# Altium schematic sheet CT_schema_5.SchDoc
size 396 x 205 mm
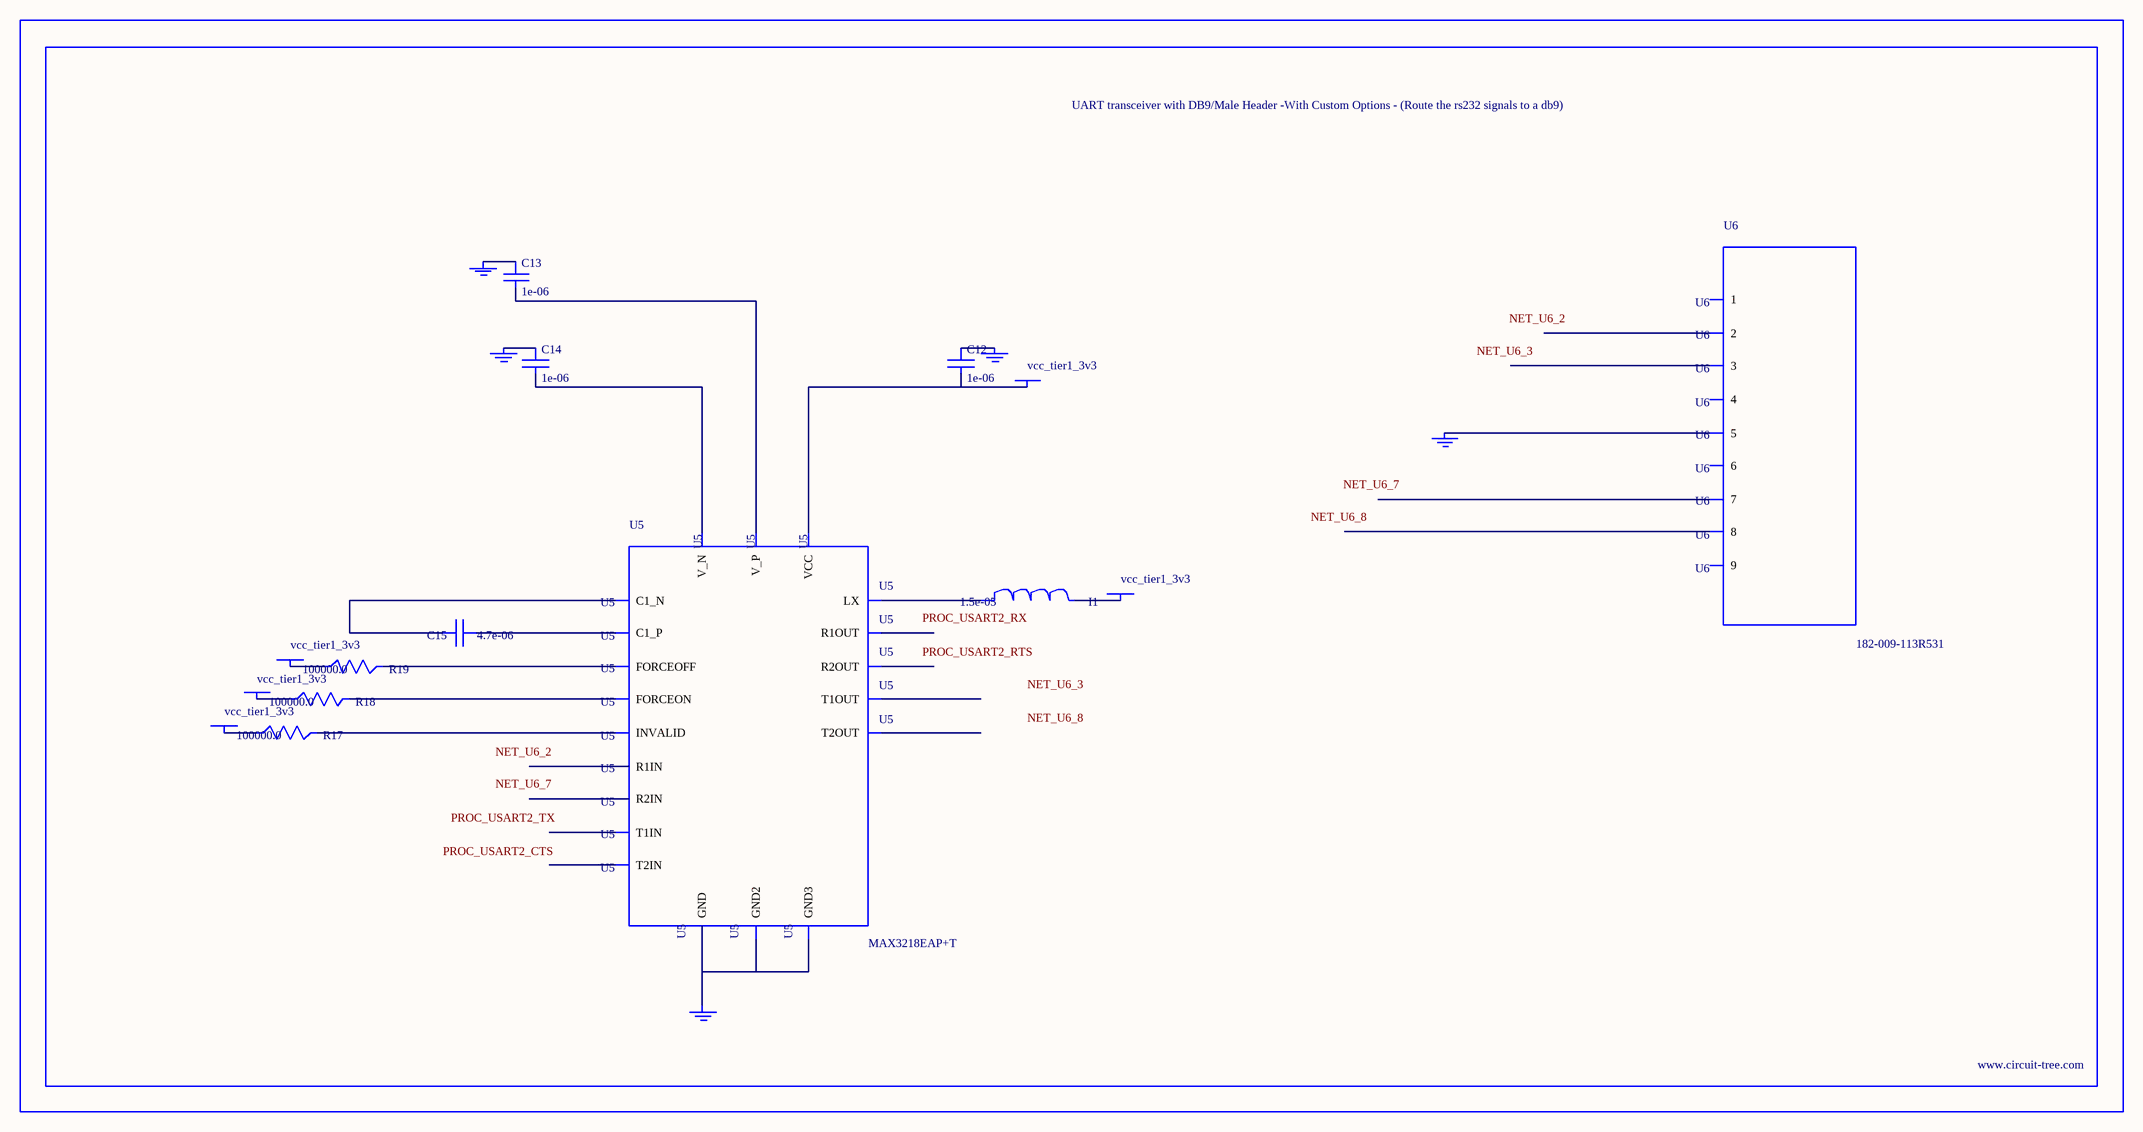
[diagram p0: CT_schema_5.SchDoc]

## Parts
BORDER4  (no value)
C12  1e-06  [C0603]
C13  1e-06  [C0603]
C14  1e-06  [C0603]
C15  4.7e-06  [C0805]
GND_INSTANCE_4_0  (no value)
GND_INSTANCE_4_1  (no value)
GND_INSTANCE_4_2  (no value)
GND_INSTANCE_4_3  (no value)
GND_INSTANCE_4_4  (no value)
I1  1.5e-05  [L1210]
POWER_INSTANCE_4_0  vcc_tier1_3v3
POWER_INSTANCE_4_1  vcc_tier1_3v3
POWER_INSTANCE_4_2  vcc_tier1_3v3
POWER_INSTANCE_4_3  vcc_tier1_3v3
POWER_INSTANCE_4_4  vcc_tier1_3v3
R17  100000.0  [R0603]
R18  100000.0  [R0603]
R19  100000.0  [R0603]
U5  MAX3218EAP+T  [SSOP-20]
U6  182-009-113R531  [182-009-MALE]

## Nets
NetC12_1: C12.1 GND_INSTANCE_4_0.0(GND)
NetC12_2: C12.2 POWER_INSTANCE_4_4.0(PWR) U5.6(VCC)
NetC13_1: C13.1 GND_INSTANCE_4_2.0(GND)
NetC13_2: C13.2 U5.19(V_P)
NetC14_1: C14.1 GND_INSTANCE_4_1.0(GND)
NetC14_2: C14.2 U5.15(V_N)
NetC15_1: C15.1 U5.18(C1_P)
NetC15_2: C15.2 U5.16(C1_N)
NetGND_INSTANCE_4_3_0: GND_INSTANCE_4_3.0(GND) U5.5(GND) U5.17(GND2) U5.20(GND3)
NetGND_INSTANCE_4_4_0: GND_INSTANCE_4_4.0(GND) U6.5
NetI1_1: I1.1 U5.1(LX)
NetI1_2: I1.2 POWER_INSTANCE_4_0.0(PWR)
NetPOWER_INSTANCE_4_1_0: POWER_INSTANCE_4_1.0(PWR) R17.1
NetPOWER_INSTANCE_4_2_0: POWER_INSTANCE_4_2.0(PWR) R18.1
NetPOWER_INSTANCE_4_3_0: POWER_INSTANCE_4_3.0(PWR) R19.1
NetR17_2: R17.2 U5.2(INVALID)
NetR18_2: R18.2 U5.3(FORCEON)
NetR19_2: R19.2 U5.4(FORCEOFF)

Not connected (* = marked no-connect by the designer): U5 7(T1IN) 8(T2IN) 9(R1OUT) 10(R2OUT) 11(R2IN) 12(R1IN) 13(T2OUT) 14(T1OUT); U6 1 2 3 4 6 7 8 9

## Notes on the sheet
- Labels drawn without touching a wire or pin: NET_U6_2, NET_U6_3, NET_U6_7, NET_U6_8, PROC_USART2_CTS, PROC_USART2_RTS, PROC_USART2_RX, PROC_USART2_TX

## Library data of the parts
BORDER4 = BORDER_PAGE4
C12-C14 = C0603C105K3RACTU
C15 = C0805C475K4RACTU
GND_INSTANCE_4_0-GND_INSTANCE_4_4 = GND
I1 = L1210R150MDWIT
POWER_INSTANCE_4_0-POWER_INSTANCE_4_4 = PWR
R17-R19 = RC0603JR-07100KL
